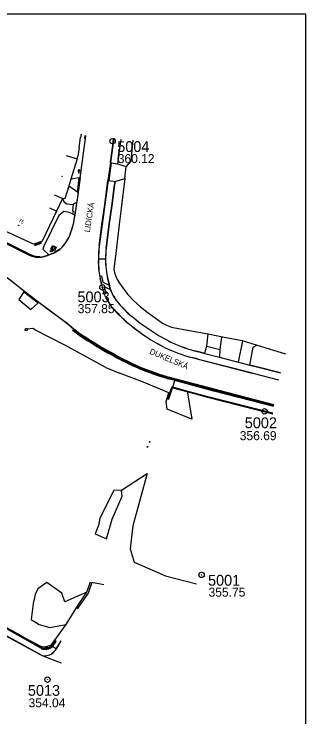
# Model space of a CAD drawing. Extents: x -590420 to -590210, y -1129531 to -1129234.
# Drawn here: x -590291.5 to -590210.4, y -1129429.2 to -1129233.9 of the extents above; entities that cross this region are included whole.
import ezdxf

# ---------------------------------------------------------------- set-up
doc = ezdxf.new("R2010")
doc.units = 0
for name, color, linetype in [('Vrstva 10', 7, 'Continuous'), ('Vrstva 11', 7, 'Continuous'), ('Vrstva 12', 7, 'Continuous'), ('Vrstva 15', 7, 'Continuous'), ('Vrstva 19', 7, 'Continuous'), ('Vrstva 23', 7, 'Continuous'), ('Vrstva 34', 7, 'Continuous'), ('Vrstva 4', 7, 'Continuous'), ('Vrstva 42', 7, 'Continuous'), ('Vrstva 43', 7, 'Continuous'), ('Vrstva 5', 7, 'Continuous'), ('Vrstva 63', 7, 'Continuous'), ('Vrstva 7', 7, 'Continuous'), ('Vrstva 9', 7, 'Continuous'), ('Vrstva B58', 7, 'Continuous'), ('Vrstva B59', 7, 'Continuous'), ('Vrstva B60', 7, 'Continuous')]:
    doc.layers.add(name, color=color, linetype=linetype)

msp = doc.modelspace()

# ---------------------------------------------------------------- linework, layer by layer
at = {"layer": 'Vrstva 10'}
for points in [[(-590266, -1129332.1), (-590277.36, -1129325.92), (-590285.55, -1129321.68), (-590286.27, -1129321.29), (-590287.73, -1129321.41)], [(-590223.99, -1129325.89), (-590216.04, -1129328.31)], [(-590249.25, -1129341.57), (-590248.45, -1129339.16), (-590255.35, -1129336.24), (-590262.23, -1129333.63)], [(-590290.26, -1129406.32), (-590284.16, -1129409.57), (-590282.97, -1129409.73), (-590281.14, -1129409.27), (-590277.06, -1129403.53), (-590274.02, -1129398.74), (-590271.27, -1129394.56), (-590270.24, -1129391.65)]]:
    msp.add_lwpolyline(points, dxfattribs=at)
at = {"layer": 'Vrstva 11'}
msp.add_lwpolyline([(-590258.46, -1129268.89), (-590259.04, -1129274.74), (-590260.32, -1129276.2)], dxfattribs=at)
at = {"layer": 'Vrstva 12'}
for points in [[(-590273.93, -1129274.11), (-590273.8, -1129273.33)], [(-590266.53, -1129392.48), (-590269.92, -1129391.85), (-590270.93, -1129394.78), (-590273.94, -1129399.13)]]:
    msp.add_lwpolyline(points, dxfattribs=at)
at = {"layer": 'Vrstva 15'}
for centre in [(-590278.17, -1129278.92), (-590275.7, -1129279.78), (-590290.2, -1129292.57)]:
    msp.add_circle(centre, 0.0438, dxfattribs=at)
at = {"layer": 'Vrstva 19'}
for p, q in [((-590273.48, -1129277.04), (-590273.73, -1129277.47)), ((-590273.73, -1129277.47), (-590273.23, -1129277.47)), ((-590273.48, -1129277.04), (-590273.23, -1129277.47)), ((-590273.48, -1129277.97), (-590273.48, -1129277.47)), ((-590273.6, -1129277.97), (-590273.35, -1129277.97)), ((-590282.48, -1129409.56), (-590282.73, -1129409.99)), ((-590282.73, -1129409.99), (-590282.23, -1129409.99)), ((-590282.48, -1129409.56), (-590282.23, -1129409.99)), ((-590282.48, -1129410.49), (-590282.48, -1129409.99)), ((-590282.6, -1129410.49), (-590282.35, -1129410.49))]:
    msp.add_line(p, q, dxfattribs=at)
at = {"layer": 'Vrstva 23'}
msp.add_lwpolyline([(-590280.68, -1129298.48), (-590280.1, -1129298.72), (-590280.35, -1129299.31), (-590280.93, -1129299.07)], close=True, dxfattribs=at)
for centre in [(-590253.82, -1129352.75), (-590254.43, -1129354.13)]:
    msp.add_circle(centre, 0.125, dxfattribs=at)
at = {"layer": 'Vrstva 34'}
msp.add_lwpolyline([(-590281.57, -1129299.86), (-590281.1, -1129299.45), (-590280.76, -1129299.65), (-590281.13, -1129299.98), (-590281.29, -1129299.61)], dxfattribs=at)
at = {"layer": 'Vrstva 4'}
for p, q in [((-590277, -1129273.15), (-590273.93, -1129274.11)), ((-590278, -1129285.08), (-590280.28, -1129284.19)), ((-590281.63, -1129287.74), (-590279.69, -1129288.66)), ((-590285.82, -1129297.75), (-590285.68, -1129298.15)), ((-590285.81, -1129297.75), (-590285.68, -1129298.14)), ((-590285.73, -1129297.72), (-590285.68, -1129297.84)), ((-590285.72, -1129297.72), (-590285.68, -1129297.83)), ((-590285.68, -1129297.83), (-590284.14, -1129297.28)), ((-590284.13, -1129297.28), (-590285.68, -1129297.84)), ((-590285.68, -1129298.14), (-590283.97, -1129297.55)), ((-590285.68, -1129298.15), (-590283.96, -1129297.55)), ((-590285.68, -1129297.83), (-590285.68, -1129297.84)), ((-590285.68, -1129298.14), (-590285.68, -1129298.15)), ((-590284.17, -1129297.18), (-590284.14, -1129297.28)), ((-590284.17, -1129297.18), (-590284.13, -1129297.28)), ((-590284.14, -1129297.28), (-590284.13, -1129297.28)), ((-590284.1, -1129297.16), (-590283.97, -1129297.55)), ((-590284.1, -1129297.16), (-590283.96, -1129297.55)), ((-590283.97, -1129297.55), (-590283.96, -1129297.55))]:
    msp.add_line(p, q, dxfattribs=at)
for points in [[(-590273.93, -1129274.11), (-590275.7, -1129279.78)], [(-590279.69, -1129288.66), (-590283.64, -1129297), (-590284.1, -1129297.16), (-590284.1, -1129297.16), (-590284.17, -1129297.18), (-590284.17, -1129297.18), (-590285.72, -1129297.72), (-590285.73, -1129297.72), (-590285.81, -1129297.75), (-590285.82, -1129297.75), (-590286.1, -1129297.85), (-590296.8, -1129292.86), (-590298.63, -1129291.83), (-590303.3, -1129289.64), (-590312.4, -1129285.24), (-590317.89, -1129282.59)], [(-590276.27, -1129281.7), (-590277.41, -1129285.25), (-590278, -1129285.08)]]:
    msp.add_lwpolyline(points, dxfattribs=at)
at = {"layer": 'Vrstva 5'}
for p, q in [((-590272.86, -1129267.22), (-590273.01, -1129268.14)), ((-590273.42, -1129270.94), (-590273.8, -1129273.33))]:
    msp.add_line(p, q, dxfattribs=at)
for points in [[(-590260.73, -1129279.51), (-590260.32, -1129276.2)], [(-590275.7, -1129279.78), (-590276.27, -1129281.7)], [(-590278, -1129285.08), (-590279.69, -1129288.66)], [(-590237.61, -1129322.72), (-590233.62, -1129323.56)], [(-590228.08, -1129324.59), (-590223.99, -1129325.89)], [(-590266, -1129332.1), (-590262.23, -1129333.63)]]:
    msp.add_lwpolyline(points, dxfattribs=at)
at = {"layer": 'Vrstva 63'}
for p, q in [((-590210.41, -1129233.85), (-590420.41, -1129233.85)), ((-590210.41, -1129530.85), (-590210.41, -1129233.85))]:
    msp.add_line(p, q, dxfattribs=at)
at = {"layer": 'Vrstva 7'}
for p, q in [((-590271.87, -1129268.42), (-590271.77, -1129267.65)), ((-590273.15, -1129279.38), (-590271.67, -1129268.46)), ((-590263.79, -1129268.31), (-590264.74, -1129275.12)), ((-590261.83, -1129268.72), (-590262.29, -1129271.91)), ((-590262.29, -1129271.91), (-590262.59, -1129274.21)), ((-590264.74, -1129275.12), (-590265.4, -1129280.11)), ((-590264.51, -1129275.18), (-590265.19, -1129280.15)), ((-590262.59, -1129274.21), (-590262.74, -1129275.47)), ((-590273.14, -1129279.4), (-590273.7, -1129283.39)), ((-590273.36, -1129279.41), (-590273.14, -1129279.4)), ((-590263.43, -1129280.42), (-590263.58, -1129281.29)), ((-590288.15, -1129300.16), (-590297.88, -1129295.25)), ((-590267.13, -1129309.27), (-590267.57, -1129307.3)), ((-590265.56, -1129307.03), (-590265.11, -1129308.96)), ((-590265.1, -1129308.96), (-590265.54, -1129307.02)), ((-590266.51, -1129309.58), (-590264.7, -1129310.43)), ((-590266.21, -1129312.17), (-590266.6, -1129311.2)), ((-590266.21, -1129312.16), (-590266.6, -1129311.2)), ((-590265.93, -1129311.47), (-590266.41, -1129311.67)), ((-590237.9, -1129326.12), (-590237.61, -1129322.72)), ((-590247.39, -1129337.56), (-590246.84, -1129335.72)), ((-590248.78, -1129340.83), (-590247.83, -1129338)), ((-590248.58, -1129340.9), (-590247.63, -1129338.07)), ((-590247.62, -1129338.07), (-590248.57, -1129340.91)), ((-590247.68, -1129337.59), (-590247.83, -1129337.99)), ((-590247.83, -1129338), (-590247.83, -1129337.99)), ((-590247.83, -1129337.99), (-590247.62, -1129338.07)), ((-590247.63, -1129338.07), (-590247.83, -1129338)), ((-590247.62, -1129338.07), (-590247.63, -1129338.07)), ((-590247.62, -1129338.07), (-590247.42, -1129337.71)), ((-590247.39, -1129337.56), (-590247.42, -1129337.71)), ((-590281.02, -1129409.41), (-590280.08, -1129408.07)), ((-590280.83, -1129409.62), (-590279.85, -1129408.23)), ((-590280.82, -1129409.64), (-590279.83, -1129408.23)), ((-590280.08, -1129408.07), (-590279.85, -1129408.23)), ((-590279.83, -1129408.23), (-590280.08, -1129408.07)), ((-590279.85, -1129408.23), (-590279.83, -1129408.23)), ((-590279.75, -1129410.27), (-590278.44, -1129408.01)), ((-590279.71, -1129410.29), (-590278.39, -1129408.02)), ((-590278.39, -1129408.02), (-590278.44, -1129408.01)), ((-590283.76, -1129409.94), (-590283.85, -1129410.23)), ((-590283.84, -1129410.23), (-590283.85, -1129410.23)), ((-590283.84, -1129410.23), (-590283.75, -1129409.95)), ((-590283.75, -1129409.95), (-590283.76, -1129409.94)), ((-590279.75, -1129410.27), (-590280.82, -1129409.64))]:
    msp.add_line(p, q, dxfattribs=at)
for points in [[(-590273.14, -1129279.4), (-590271.66, -1129268.45), (-590271.55, -1129267.64)], [(-590264.74, -1129275.12), (-590264.72, -1129275.1), (-590263.78, -1129268.31)], [(-590288.27, -1129300.4), (-590298.02, -1129295.47), (-590300.04, -1129294.45), (-590304.43, -1129292.29), (-590311.08, -1129288.92), (-590319.04, -1129284.98), (-590334.63, -1129277.2), (-590335.79, -1129276.63), (-590337.94, -1129275.57), (-590341.15, -1129273.96), (-590343.82, -1129272.62), (-590345.62, -1129271.67)], [(-590262.59, -1129274.21), (-590262.58, -1129274.19), (-590262.27, -1129271.92), (-590262.29, -1129271.91)], [(-590264.72, -1129275.1), (-590264.51, -1129275.18), (-590264.74, -1129275.12)], [(-590264.51, -1129275.18), (-590262.74, -1129275.47), (-590260.32, -1129276.2)], [(-590273.36, -1129279.41), (-590275.7, -1129279.78)], [(-590273.87, -1129283.38), (-590273.36, -1129279.41)], [(-590273.14, -1129279.4), (-590273.15, -1129279.38), (-590273.36, -1129279.41)], [(-590267.86, -1129298.26), (-590267.07, -1129292.36), (-590266.31, -1129286.77), (-590265.4, -1129280.11)], [(-590265.4, -1129280.11), (-590265.38, -1129280.15), (-590266.29, -1129286.77), (-590267.06, -1129292.36), (-590267.85, -1129298.32)], [(-590263.58, -1129281.29), (-590264.35, -1129287.18), (-590265.04, -1129292.14), (-590265.92, -1129299.04)], [(-590265.91, -1129299.04), (-590265.03, -1129292.14), (-590264.34, -1129287.18), (-590263.57, -1129281.31), (-590263.43, -1129280.42)], [(-590265.38, -1129280.15), (-590265.19, -1129280.15), (-590265.4, -1129280.11)], [(-590265.19, -1129280.15), (-590263.43, -1129280.42), (-590260.73, -1129279.51)], [(-590273.87, -1129283.38), (-590276.27, -1129281.7)], [(-590273.7, -1129283.39), (-590273.96, -1129285.4), (-590274.84, -1129291.08), (-590275.06, -1129292.31)], [(-590278, -1129285.08), (-590277.6, -1129286.12), (-590276.8, -1129286.57), (-590275.05, -1129286.82)], [(-590273.71, -1129283.42), (-590273.98, -1129285.39), (-590274.14, -1129286.45), (-590274.65, -1129289.79), (-590274.85, -1129291.08), (-590275.08, -1129292.3)], [(-590274.14, -1129286.45), (-590274.56, -1129286.45), (-590275.05, -1129286.82), (-590275.22, -1129288.5), (-590274.96, -1129288.63), (-590275.23, -1129289.4), (-590274.65, -1129289.79)], [(-590275.23, -1129289.4), (-590276.16, -1129288.99), (-590277.67, -1129288.75), (-590279.03, -1129289.87), (-590283.2, -1129298.4), (-590283.48, -1129299.2), (-590281.79, -1129300.79)], [(-590288.27, -1129300.4), (-590288.15, -1129300.16)], [(-590284.23, -1129301.3), (-590284.18, -1129301.53), (-590284.95, -1129301.58), (-590285.48, -1129301.51), (-590285.98, -1129301.37), (-590286.47, -1129301.2), (-590287.39, -1129300.85), (-590288.27, -1129300.4)], [(-590284.23, -1129301.3), (-590284.83, -1129301.34), (-590285.36, -1129301.27), (-590285.86, -1129301.13), (-590286.35, -1129300.96), (-590287.27, -1129300.61), (-590288.15, -1129300.16)], [(-590278.8, -1129299.24), (-590280.54, -1129300.33), (-590281.79, -1129300.79), (-590282.45, -1129301.03), (-590284.18, -1129301.53)], [(-590284.18, -1129301.53), (-590282.45, -1129301.04), (-590280.53, -1129300.35), (-590278.79, -1129299.25)], [(-590268.03, -1129301.84), (-590266.08, -1129301.88)], [(-590298.27, -1129303.43), (-590294.68, -1129306.1), (-590292.55, -1129307.71), (-590288.63, -1129310.87), (-590284.63, -1129313.91), (-590282.5, -1129315.5), (-590279.13, -1129317.97), (-590276.75, -1129319.72), (-590274.87, -1129321.35)], [(-590267.67, -1129306.7), (-590267.17, -1129306.64), (-590266.79, -1129308.36), (-590265.06, -1129309.17)], [(-590267.55, -1129307.31), (-590267.12, -1129309.28), (-590266.89, -1129310.26)], [(-590264.56, -1129310.89), (-590264.7, -1129310.43), (-590264.85, -1129309.94), (-590265.06, -1129309.17), (-590265.11, -1129308.96)], [(-590265.1, -1129308.96), (-590264.85, -1129309.93), (-590264.53, -1129310.9)], [(-590288.75, -1129311.09), (-590290.12, -1129313.15), (-590286.87, -1129316), (-590284.78, -1129314.11)], [(-590288.63, -1129310.87), (-590288.75, -1129311.09), (-590284.78, -1129314.11), (-590284.63, -1129313.91)], [(-590284.63, -1129313.91), (-590282.44, -1129315.61), (-590279.19, -1129317.98), (-590276.79, -1129319.75), (-590274.98, -1129321.32), (-590274.87, -1129321.35)], [(-590248.61, -1129324.72), (-590251.46, -1129323.2), (-590253.98, -1129321.57), (-590256.45, -1129319.83), (-590258.76, -1129317.95)], [(-590248.6, -1129324.7), (-590251.46, -1129323.19), (-590253.98, -1129321.55), (-590256.44, -1129319.82), (-590258.76, -1129317.95)], [(-590275.19, -1129321.76), (-590275.06, -1129321.56), (-590274.87, -1129321.35)], [(-590233.62, -1129323.56), (-590233.85, -1129323.62), (-590234.31, -1129327.08)], [(-590238.46, -1129328.17), (-590238.53, -1129328.04), (-590237.9, -1129326.12), (-590234.31, -1129327.08), (-590234.42, -1129329.04), (-590234.45, -1129329.22)], [(-590229.14, -1129330.59), (-590227.98, -1129324.69), (-590228.08, -1129324.59)], [(-590225.96, -1129331.42), (-590225.08, -1129326.47), (-590224.06, -1129325.87), (-590223.99, -1129325.89)], [(-590238.46, -1129328.17), (-590239.44, -1129327.91), (-590241.38, -1129327.42)], [(-590241.38, -1129327.44), (-590239.43, -1129327.93), (-590238.46, -1129328.17)], [(-590238.46, -1129328.17), (-590234.45, -1129329.22), (-590229.21, -1129330.57), (-590229.14, -1129330.59), (-590225.96, -1129331.42), (-590224.03, -1129331.92), (-590217.43, -1129333.61)], [(-590217.93, -1129335.6), (-590224.7, -1129333.84), (-590225.6, -1129333.63), (-590239.87, -1129329.94), (-590240.94, -1129329.65), (-590242.34, -1129329.29)], [(-590217.91, -1129335.59), (-590224.7, -1129333.83), (-590225.61, -1129333.61), (-590239.86, -1129329.92), (-590240.94, -1129329.63), (-590242.32, -1129329.27)], [(-590256.79, -1129332.07), (-590256.88, -1129332.3), (-590256.79, -1129332.06)], [(-590217.43, -1129333.6), (-590224.03, -1129331.92), (-590225.96, -1129331.42)], [(-590219.43, -1129342.91), (-590235.98, -1129338.62), (-590246.84, -1129335.72), (-590248.69, -1129335.22)], [(-590219.36, -1129342.67), (-590235.95, -1129338.37), (-590246.77, -1129335.5), (-590248.64, -1129335)], [(-590219.28, -1129342.43), (-590235.88, -1129338.14), (-590248.56, -1129334.74)], [(-590247.69, -1129337.55), (-590247.87, -1129337.96), (-590248.81, -1129340.83)], [(-590247.39, -1129337.56), (-590247.69, -1129337.55)], [(-590247.39, -1129337.56), (-590247.68, -1129337.59)], [(-590247.42, -1129337.71), (-590247.42, -1129337.7), (-590247.39, -1129337.6), (-590247.39, -1129337.56)], [(-590219.61, -1129344.94), (-590237.71, -1129340.32), (-590243.47, -1129338.78), (-590247.42, -1129337.7)], [(-590247.42, -1129337.71), (-590243.47, -1129338.79), (-590237.71, -1129340.33), (-590219.61, -1129344.95)], [(-590219.59, -1129344.82), (-590237.69, -1129340.2), (-590243.45, -1129338.65), (-590247.39, -1129337.56)], [(-590219.59, -1129344.84), (-590237.69, -1129340.22), (-590243.45, -1129338.68), (-590247.39, -1129337.6)], [(-590243.47, -1129338.79), (-590243.33, -1129339.1), (-590242.07, -1129346.46), (-590248.93, -1129343.63), (-590249.25, -1129341.57)], [(-590248.81, -1129340.83), (-590248.57, -1129340.91), (-590248.58, -1129340.9)], [(-590248.58, -1129340.9), (-590248.78, -1129340.83), (-590248.81, -1129340.83)], [(-590388.29, -1129353.97), (-590379.87, -1129358.7), (-590371.52, -1129363.35), (-590359.77, -1129369.89), (-590358.02, -1129370.87), (-590357.16, -1129371.35), (-590355.52, -1129372.26), (-590351, -1129374.8), (-590342.74, -1129379.37), (-590332.57, -1129385.02), (-590330.82, -1129386.01), (-590319.93, -1129392.08), (-590307.83, -1129398.82), (-590295.9, -1129405.45), (-590293.78, -1129406.63), (-590284.05, -1129411.95)], [(-590261.67, -1129366.17), (-590254.5, -1129361.57), (-590258.51, -1129376.06), (-590259.27, -1129382.5), (-590258.13, -1129386.23), (-590249.4, -1129389.95), (-590240.78, -1129392.2)], [(-590284.03, -1129411.94), (-590293.77, -1129406.61), (-590295.91, -1129405.41), (-590307.82, -1129398.81), (-590319.92, -1129392.05), (-590330.83, -1129385.99), (-590332.57, -1129385.02)], [(-590271.27, -1129394.56), (-590274.27, -1129395.83), (-590277.43, -1129397.23), (-590278.19, -1129394.85), (-590282.36, -1129391.82), (-590284.93, -1129393.56), (-590285.59, -1129395.18), (-590286.21, -1129397.7), (-590286.75, -1129402.11), (-590284.49, -1129403.47), (-590281.55, -1129404.36), (-590277.06, -1129403.53)], [(-590283.85, -1129410.23), (-590294.91, -1129403.98), (-590302.41, -1129399.73)], [(-590283.76, -1129409.94), (-590294.76, -1129403.72), (-590302.26, -1129399.47)], [(-590284.05, -1129411.95), (-590283, -1129412.41), (-590278.38, -1129414.2)]]:
    msp.add_lwpolyline(points, dxfattribs=at)
for points in [[(-590271.66, -1129268.45), (-590271.67, -1129268.46), (-590271.87, -1129268.42)], [(-590273.7, -1129283.39), (-590273.87, -1129283.38), (-590273.71, -1129283.42)], [(-590280.23, -1129299.67), (-590281.27, -1129299.16), (-590280.84, -1129298.14), (-590279.81, -1129298.66)], [(-590288.24, -1129321.18), (-590287.73, -1129321.41), (-590287.97, -1129321.92), (-590288.47, -1129321.69)], [(-590265.82, -1129379.7), (-590264.22, -1129374.27), (-590261.46, -1129367.83), (-590261.67, -1129366.17), (-590263.77, -1129366.29), (-590267.69, -1129373.97), (-590268.07, -1129376.04), (-590268.96, -1129378.3)]]:
    msp.add_lwpolyline(points, close=True, dxfattribs=at)
for centre, radius, start, end in [((-590282.85, -1129407.3), 3.1, 251.184, 310.9169), ((-590282.87, -1129407.28), 3.11, 251.6553, 310.9329), ((-590282.86, -1129407.28), 2.82, 251.6553, 310.8406)]:
    msp.add_arc(centre, radius, start, end, dxfattribs=at)
for centre, major_axis, ratio, start_param, end_param in [((-590296.03, -1129287.18), (3.35, 22.12), 0.963792, 4.45136, 4.626358), ((-590295.63, -1129287.41), (-2.57, 21.09), 0.994846, 4.175451, 4.358969), ((-590285.09, -1129291.7), (5.02, 8.71), 0.973673, 4.367691, 4.777061), ((-590285.21, -1129291.67), (3.59, 9.33), 0.9918, 4.215594, 4.628949), ((-590237.01, -1129301.72), (-12.68, -28.56), 0.992994, 5.016394, 5.131341), ((-590234.54, -1129300.97), (-3.85, -42.39), 0.785081, 4.721339, 4.804206), ((-590240.79, -1129301.54), (-4.44, -26.39), 0.943583, 4.776142, 4.963532), ((-590238.39, -1129301.71), (-7.16, -27.42), 0.97481, 4.867398, 5.044669), ((-590244.96, -1129302.54), (-17.82, -14.77), 0.998119, 5.560173, 5.710569), ((-590245.17, -1129302.67), (-18.46, -13.55), 0.9971, 5.612549, 5.765074), ((-590223.24, -1129299.6), (23.38, -36.69), 0.985672, 4.254247, 4.323932), ((-590231.36, -1129300.9), (13.33, -33.64), 0.95793, 4.437282, 4.520529), ((-590235.03, -1129299.85), (-0.75, -35.05), 0.949335, 4.889263, 4.947025), ((-590261.42, -1129303.67), (2.2, -16.67), 0.395118, 4.759408, 4.880236), ((-590251.22, -1129306.1), (12.85, -10.06), 0.990003, 4.007241, 4.130414), ((-590258.51, -1129308.79), (4.46, -12.67), 0.587324, 4.569939, 4.717451), ((-590243.09, -1129300.53), (8.62, -26.69), 0.9209, 4.854033, 4.926474), ((-590247.36, -1129303.81), (19, -8.14), 0.99568, 3.966006, 4.06336), ((-590253.18, -1129306.07), (-2.51, -12.15), 0.995153, 5.314575, 5.573083), ((-590251.12, -1129305.15), (12.66, -7.4), 0.992021, 4.079159, 4.295315), ((-590249.32, -1129303.31), (17.46, -8.18), 0.994497, 4.170312, 4.275674), ((-590249.31, -1129303.39), (17.59, -7.74), 0.99499, 4.143369, 4.248731), ((-590233.35, -1129289.28), (34.92, -16.57), 0.990468, 4.276708, 4.432689), ((-590233.99, -1129289.66), (37.65, 0.08), 0.998043, 3.832043, 3.992037), ((-590225.62, -1129280.97), (2.77, -51.73), 0.998136, 5.390865, 5.499671), ((-590225.64, -1129279.8), (36.96, -42.89), 0.927183, 4.748066, 4.847568), ((-590213.59, -1129263.49), (66.5, -32.53), 0.983054, 4.478744, 4.569277), ((-590221.42, -1129273.75), (57.46, -17.68), 0.996082, 4.311194, 4.42228), ((-590248.44, -1129287.62), (24.64, -35.77), 0.998327, 5.014733, 5.165931), ((-590234.97, -1129268.41), (64.5, -18.13), 0.992626, 4.342709, 4.440348), ((-590242.57, -1129279.48), (-21.88, -48.14), 0.999231, 6.052576, 6.174999), ((-590232.5, -1129291.35), (38.61, -6.91), 0.997017, 4.286341, 4.44123), ((-590232.18, -1129290.66), (20.08, -34.49), 0.999194, 5.154613, 5.306021), ((-590237.91, -1129278.35), (55.78, -13.91), 0.986665, 4.366256, 4.483062), ((-590236.42, -1129274.43), (35.17, -49.94), 0.996597, 5.089584, 5.198799), ((-590220.21, -1129246.18), (0, -93.24), 0.999151, 5.723909, 5.796045), ((-590228.53, -1129260.6), (-36.19, -67.2), 0.99936, 6.210138, 6.298092), ((-590230.76, -1129288.46), (40.09, -6.34), 0.995394, 4.413142, 4.603807), ((-590231.3, -1129289.86), (38.92, -1.88), 0.997726, 4.300512, 4.498863), ((-590228.62, -1129282.1), (48.76, 6.42), 0.999021, 4.142871, 4.298836), ((-590229.89, -1129285.42), (45.38, 4.68), 0.998901, 4.165831, 4.333737), ((-590220.67, -1129248.39), (79.8, -52.7), 0.95435, 4.797715, 4.88076), ((-590228.45, -1129265.43), (59.37, -43.46), 0.986857, 4.831976, 4.939347), ((-590227.5, -1129263), (60.19, -46.99), 0.981157, 4.866589, 4.969455), ((-590222.83, -1129254.72), (53.66, -65.33), 0.995359, 5.087078, 5.180284), ((-590221.41, -1129246.34), (82.39, -43.54), 0.995102, 4.806656, 4.899707), ((-590225.93, -1129258.01), (75.76, -33.27), 0.9696, 4.730854, 4.835582), ((-590221.19, -1129245.12), (-48.45, -80.22), 0.999899, 0.155028, 0.246944), ((-590222.3, -1129247.16), (87.75, -36.88), 0.965383, 4.724038, 4.81543), ((-590282.87, -1129407.26), (2.48, -1.38), 0.994407, 4.899341, 5.928471), ((-590283.14, -1129408.3), (3.93, 0), 0.995387, 4.899167, 5.753597), ((-590283.06, -1129408.37), (3.62, 1.38), 0.992063, 4.523519, 5.393112), ((-590282.94, -1129409.85), (2.36, -0.47), 0.986502, 4.430401, 5.140486), ((-590282.98, -1129409.94), (2.25, -0.58), 0.97285, 4.486111, 5.204031)]:
    msp.add_ellipse(centre, major_axis=major_axis, ratio=ratio, start_param=start_param, end_param=end_param, dxfattribs=at)
at = {"layer": 'Vrstva 9'}
msp.add_line((-590233.62, -1129323.56), (-590228.08, -1129324.59), dxfattribs=at)
for points in [[(-590273.42, -1129270.94), (-590273.01, -1129268.14)], [(-590260.73, -1129279.51), (-590261.78, -1129287.92), (-590262.27, -1129292.35), (-590263.22, -1129300.37), (-590263.75, -1129304.67), (-590263.62, -1129305.66), (-590263.35, -1129306.48), (-590262.83, -1129307.59), (-590262.21, -1129308.62), (-590260.83, -1129310.61), (-590259.92, -1129311.78), (-590258.22, -1129313.6), (-590257.43, -1129314.33), (-590256.37, -1129315.25), (-590254.25, -1129316.88), (-590252.26, -1129318.29), (-590250.21, -1129319.77), (-590249.1, -1129320.29), (-590247.74, -1129320.83), (-590245.31, -1129321.37), (-590237.61, -1129322.72)]]:
    msp.add_lwpolyline(points, dxfattribs=at)
at = {"layer": 'Vrstva B60'}
for centre, radius in [((-590264.12, -1129269.18), 0.75), ((-590264.12, -1129269.18), 0.0358), ((-590266.95, -1129309.8), 0.75), ((-590266.95, -1129309.8), 0.0358), ((-590221.89, -1129344.27), 0.75), ((-590221.89, -1129344.27), 0.0358), ((-590239.39, -1129389.73), 0.75), ((-590239.39, -1129389.73), 0.0358), ((-590282.2, -1129418.84), 0.75), ((-590282.2, -1129418.84), 0.0358)]:
    msp.add_circle(centre, radius, dxfattribs=at)

# ---------------------------------------------------------------- texts
at = {"layer": 'Vrstva 42'}
for s, rotation, p in [('LIDICKÁ', 81.4019, (-590270.44, -1129294.58)), ('DUKELSKÁ', 337.2198, (-590253.99, -1129328.23))]:
    msp.add_text(s, height=1.6, rotation=rotation, dxfattribs=at).set_placement(p)
at = {"layer": 'Vrstva 43'}
msp.add_text('75', height=1, rotation=334.8801, dxfattribs=at).set_placement((-590290.42, -1129291.56))
at = {"layer": 'Vrstva B58'}
for s, p in [('360.12', (-590262.69, -1129275.27)), ('357.85', (-590273.8, -1129316.98)), ('356.69', (-590228.79, -1129352.28)), ('355.75', (-590237.46, -1129395.78)), ('354.04', (-590287.46, -1129426.53))]:
    msp.add_text(s, height=2.5, dxfattribs=at).set_placement(p)
at = {"layer": 'Vrstva B59'}
for s, p in [('5004', (-590262.82, -1129272.18)), ('5003', (-590273.87, -1129313.96)), ('5002', (-590227.39, -1129348.95)), ('5001', (-590237.6, -1129392.73)), ('5013', (-590287.65, -1129423.33))]:
    msp.add_text(s, height=3, dxfattribs=at).set_placement(p)

doc.saveas('drawing.dxf')
